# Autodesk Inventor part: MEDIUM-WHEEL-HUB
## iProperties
Created: 2007-08
Part Number: MEDIUM-WHEEL-HUB
Material: ABS Plastic
Document SubType Name: Modeling
Density: 1.06 g/cm^3
Mass: 42.8255 g
Surface Area: 324.402 cm^2
Volume: 40.4014 cm^3
